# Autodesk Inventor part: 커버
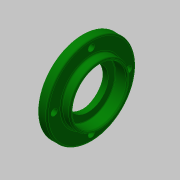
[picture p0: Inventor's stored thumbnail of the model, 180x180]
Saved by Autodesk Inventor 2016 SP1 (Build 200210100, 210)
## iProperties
Created: 2018-11
Part Number: 커버
Material: 알루미늄 6061
Document SubType Name: Modeling
Designer: mduedu
Density: 1 g/cm^3
Appearance: 진녹색
Author: mduedu
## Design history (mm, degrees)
sketch "스케치1"
  geometry: L1 (0, 0)-(2, 0); L2 (2, 0)-(2, 20); L3 (2, 20)-(0, 20); L4 (0, 20)-(0, 0); L5 (2, 0)-(8, 0); L6 (8, 0)-(8, 31); L7 (8, 31)-(2, 31); L8 (2, 31)-(2, 0); L9 (8, 0)-(14, 0); L10 (14, 0)-(14, 21); L11 (14, 21)-(8, 21); L12 (8, 21)-(8, 0)
  constraints: 24 end point, 6 parallel, 3 horizontal, 3 perpendicular
  dimensions: "d0" = 62 diameter of L7 L5; "d2" = 42 diameter of L11 L9; "d3" = 40 diameter of L3 L1; "d4" = 2 distance of L2.end L3.end; "d5" = 6 distance of L6.end L7.end; "d6" = 14 distance between parallel lines of L10 L4
revolve "회전1" sketch "스케치1" stored, may be unused: angle "d7" = 90 deg
sketch "스케치2"
  geometry: L1 (0, -20)-(0, 20) reference; L2 (0, 20)-(2, 20) reference; L3 (2, 20)-(2, 31) reference; L4 (2, 31)-(8, 31) reference; L5 (8, 31)-(8, 21) reference; L6 (8, 21)-(14, 21) reference; L7 (14, 21)-(14, -21) reference; L8 (14, -21)-(8, -21) reference; L9 (8, -21)-(8, -31) reference; L10 (8, -31)-(2, -31) reference; L11 (2, -31)-(2, -20) reference; L12 (2, -20)-(0, -20) reference; L13 (0, 0)-(2, 0); L14 (2, 0)-(2, 16.5); L15 (2, 16.5)-(0, 16.5); L16 (0, 16.5)-(0, 0); L17 (2, 0)-(5.7, 0); L18 (5.7, 0)-(5.7, 14); L19 (5.7, 14)-(2, 14); L20 (2, 14)-(2, 0); L21 (5.7, 0)-(14, 0); L22 (14, 0)-(14, 19); L23 (14, 19)-(5.7, 19); L24 (5.7, 19)-(5.7, 0)
  constraints: 24 end point, 6 parallel, 3 horizontal, 3 perpendicular, 1 point on line
  dimensions: "d8" = 38 diameter of L23 L21; "d10" = 28 diameter of L19 L17; "d11" = 33 diameter of L15 L13; "d12" = 2 distance of L14.end L15.end; "d13" = 8.3 distance of L22.end L23.end
revolve "회전2" sketch "스케치2" stored, may be unused: angle "d14" = 90 deg
fillet "모깎기1" dims "d15" = 0.3
chamfer "모따기1" distance "d16" = 0.8; stored, may be unused: second distance "d17" = 2, angle "d18" = 30 deg
fillet "모깎기2" dims "d19" = 1
chamfer "모따기2" distance "d20" = 0.5; stored, may be unused: second distance "d21" = 2, angle "d22" = 30 deg
sketch "스케치3" dims "d23" = 52
  geometry: 6 further points
  constraints: 2 vertical alignment, 1 coincident, 7 other
  dimensions: "d26" = 360 deg dimension on point (0, 0) point (0, 26) (derived)
sketch "스케치4"
  geometry: 4 further points
  constraints: 4 other
hole "구멍1" sketch "스케치4" at (-26, 0), (0, -26), (26, 0), (0, 26) diameter "d28" = 4.5; stored, may be unused: countersink angle "d32" = 90 deg, drill point angle "d34" = 0 deg; dims "d29" = 6, "d30" = 8, "d31" = 4.6, "d33" = 8
node "솔리드1"
node "절단 모서리 투영1"
